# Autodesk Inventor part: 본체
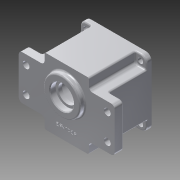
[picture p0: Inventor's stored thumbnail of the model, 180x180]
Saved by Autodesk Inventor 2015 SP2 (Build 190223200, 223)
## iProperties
Created: 2015-06
Part Number: 본체
Material: 알루미늄 6061
Document SubType Name: Modeling
Designer: AMC
Density: 2.7 g/cm^3
Appearance: 알루미늄 - 평지
Mass: 759.107 g
Surface Area: 671.501 cm^2
Volume: 281.151 cm^3
Author: AMC
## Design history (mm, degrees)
sketch "스케치1"
  geometry: L1 (65, 30)-(-65, 30); L2 (-65, 30)-(-65, -30); L3 (-65, -30)-(65, -30); L4 (65, -30)-(65, 30); 3 further points
  constraints: 8 end point, 2 midpoint, 2 parallel, 1 horizontal, 1 horizontal alignment, 1 perpendicular, 1 vertical alignment
  dimensions: "d0" = 130 distance of L1.start L1.end; "d1" = 60 distance of L1.end L2.end
extrude "돌출1" new body sketch "스케치1" distance "d2" = 12; taper "d3" = 0 deg
sketch "스케치2"
  geometry: L1 (-65, -30)-(-65, 30) reference; L2 (-65, 30)-(65, 30) reference; L3 (65, 30)-(65, -30) reference; L4 (65, -30)-(-65, -30) reference; L5 (-65, 30)-(65, 30) reference; L6 (-30, 45)-(30, 45); L7 (30, 45)-(30, 30); L8 (30, 30)-(-30, 30); L9 (-30, 30)-(-30, 45); 2 further points
  constraints: 8 end point, 2 parallel, 1 horizontal, 1 midpoint, 1 perpendicular, 1 point on line, 1 vertical alignment
  dimensions: "d4" = 60 distance of L6.start L6.end; "d5" = 45 distance from line of point (0, 0) L6
extrude "돌출2" join sketch "스케치2" distance "d6" = 70; taper "d7" = 0 deg
sketch "스케치3"
  geometry: L1 (-30, 45)-(30, 45) reference; L2 (30, 45)-(30, 30) reference; L3 (30, 30)-(65, 30) reference; L4 (65, 30)-(65, -30) reference; L5 (65, -30)-(-65, -30) reference; L6 (-65, -30)-(-65, 30) reference; L7 (-65, 30)-(-30, 30) reference; L8 (-30, 30)-(-30, 45) reference; L9 (-30, -30)-(30, -30); L10 (30, -30)-(30, -45); L11 (30, -45)-(-30, -45); L12 (-30, -45)-(-30, -30); 2 further points
  constraints: 8 end point, 2 parallel, 1 horizontal, 1 midpoint, 1 perpendicular, 1 point on line, 1 vertical alignment
  dimensions: "d8" = 45 distance from line of point (0, 0) L11; "d9" = 60 distance of L10.end L11.end
extrude "돌출3" join sketch "스케치3" distance "d10" = 70; taper "d11" = 0 deg
sketch "스케치4"
  geometry: L1 (-30, 45)-(30, 45) reference; L2 (30, 45)-(30, 30) reference; L3 (30, 30)-(-30, 30) reference; L4 (-30, 30)-(-30, 45) reference; L5 (30, -45)-(-30, -45) reference; L6 (-30, -45)-(-30, -30) reference; L7 (-30, -30)-(30, -30) reference; L8 (30, -30)-(30, -45) reference; L9 (45, -45)-(-45, -45); L10 (-45, -45)-(-45, 45); L11 (-45, 45)-(45, 45); L12 (45, 45)-(45, -45); 3 further points
  constraints: 8 end point, 2 collinear, 2 midpoint, 2 parallel, 1 horizontal, 1 horizontal alignment, 1 perpendicular, 1 vertical alignment
  dimensions: "d12" = 90 distance of L9.start L9.end; "d13" = 45 distance from line of point (0, 0) L10
extrude "돌출4" join sketch "스케치4" distance "d14" = 7; taper "d15" = 0 deg
sketch "스케치5"
  geometry: L1 (-30, 30)-(30, 30) reference; L2 (-30, 30)-(30, 30); L3 (30, 30)-(30, -30); L4 (30, -30)-(-30, -30); L5 (-30, -30)-(-30, 30); 1 further point
  constraints: 8 end point, 2 parallel, 1 horizontal, 1 perpendicular
  dimensions: "d17" = 60 distance of L2.end L3.end; "d18" = 30 distance from line of point (0, 0) L3
extrude "돌출5" join sketch "스케치5" stored distance "d19" = 7; taper "d20" = 0 deg
sketch "스케치6"
  geometry: L1 (45, -45)-(45, 45) reference; L2 (30, 30)-(30, -30); L3 (30, 30)-(45, 30); L4 (45, 30)-(45, -30); L5 (45, -30)-(30, -30); L6 (45, -45)-(45, 45) reference; 1 further point
  constraints: 8 end point, 2 point on line, 1 perpendicular, 1 vertical
extrude "돌출6" join sketch "스케치6" stored distance "d21" = 7; taper "d22" = 0 deg
sketch "스케치8"
  geometry: L1 (30, -30)-(30, -45) reference; L2 (30, -45)-(-30, -45) reference; L3 (-30, -45)-(-30, -30) reference; L4 (-30, -30)-(-65, -30) reference; L5 (-65, -30)-(-65, 30) reference; L6 (-65, 30)-(-30, 30) reference; L7 (-30, 30)-(-30, 45) reference; L8 (-30, 45)-(30, 45) reference; L9 (30, 45)-(30, 30) reference; L10 (30, 30)-(65, 30) reference; L11 (65, 30)-(65, -30) reference; L12 (65, -30)-(30, -30) reference; C1 r 4.5 at (-55, 17.5); 1 further point
  constraints: 1 centre point
  dimensions: "d23" = 9 diameter of C1; "d25" = 55 horizontal distance of C1.centre point (0, 0); "d26" = 17.5 vertical distance of point (0, 0) C1.centre
extrude "돌출7" cut sketch "스케치8" distance "d27" = 28; taper "d28" = 0 deg
sketch "스케치9"
  geometry: L1 (-45, -45)-(-45, -30) reference; L2 (-45, -30)-(-45, 30) reference; L3 (-45, 30)-(-45, 45) reference; L4 (-45, 45)-(-30, 45) reference; L5 (-30, 45)-(30, 45) reference; L6 (30, 45)-(45, 45) reference; L7 (45, 45)-(45, 30) reference; L8 (45, 30)-(45, -30) reference; L9 (45, -30)-(30, -30) reference; L10 (30, -30)-(30, -45) reference; L11 (45, -45)-(30, -45) reference; L12 (45, -30)-(45, -45) reference; L13 (-30, -45)-(-45, -45) reference; L14 (-30, -45)-(-30, -30) reference; L15 (-30, -30)-(-45, -30) reference; L16 (-45, 30)-(-30, 30) reference; L17 (-30, 30)-(-30, 45) reference; L18 (30, 45)-(30, 30) reference; L19 (30, 30)-(45, 30) reference; L20 (30, -45)-(-30, -45) reference; C1 r 3.5 at (37, -37); 1 further point
  constraints: 1 centre point
  dimensions: "d29" = 7 diameter of C1; "d30" = 37 horizontal distance of point (0, 0) C1.centre; "d31" = 37 horizontal distance of point (0, 0) C1.centre
extrude "돌출8" cut sketch "스케치9" distance "d32" = 28; taper "d33" = 0 deg
sketch "스케치10"
  geometry: L1 (30, -30)-(30, -45) reference; L2 (30, -45)-(-30, -45) reference; L3 (-30, -45)-(-30, -30) reference; L4 (-30, -30)-(-65, -30) reference; L5 (-65, -30)-(-65, 30) reference; L6 (-65, 30)-(-30, 30) reference; L7 (-30, 30)-(-30, 45) reference; L8 (-30, 45)-(30, 45) reference; L9 (30, 45)-(30, 30) reference; L10 (30, 30)-(65, 30) reference; L11 (65, 30)-(65, -30) reference; L12 (65, -30)-(30, -30) reference; C1 r 4.5 at (55, -17.5) reference; C2 r 4.5 at (-55, -17.5) reference; C3 r 4.5 at (55, 17.5) reference; C4 r 4.5 at (-55, 17.5) reference; C5 r 25 at (0, 11); 1 further point
  constraints: 1 centre point, 1 vertical alignment
  dimensions: "d34" = 50 diameter of C5; "d35" = 11 distance of point (0, 0) C5.centre
extrude "돌출9" join sketch "스케치10" distance "d36" = 7; taper "d37" = 0 deg
sketch "스케치11"
  geometry: C1 r 25 at (0, 0) reference; C2 r 16 at (0, 0); 1 further point
  constraints: 1 centre point, 1 coincident
  dimensions: "d38" = 32 diameter of C2
extrude "돌출10" cut sketch "스케치11" distance "d39" = 8; taper "d40" = 0 deg
sketch "스케치12"
  geometry: L1 (30, -41)-(30, -56) reference; L2 (30, -56)-(-30, -56) reference; L3 (-30, -56)-(-30, -41) reference; L4 (-30, -41)-(-65, -41) reference; L5 (-65, -41)-(-65, 19) reference; L6 (-65, 19)-(-30, 19) reference; L7 (-30, 19)-(-30, 34) reference; L8 (-30, 34)-(30, 34) reference; L9 (30, 34)-(30, 19) reference; L10 (30, 19)-(65, 19) reference; L11 (65, 19)-(65, -41) reference; L12 (65, -41)-(30, -41) reference; C1 r 16 at (0, 0) reference; C2 r 4.5 at (55, -28.5) reference; C3 r 4.5 at (-55, -28.5) reference; C4 r 4.5 at (55, 6.5) reference; C5 r 4.5 at (-55, 6.5) reference; C6 r 12.5 at (0, 0); 1 further point
  constraints: 1 centre point, 1 coincident
  dimensions: "d41" = 25 diameter of C6
extrude "돌출11" cut sketch "스케치12" distance "d42" = 5; taper "d43" = 0 deg
sketch "스케치13"
  geometry: L1 (30, -41)-(30, -56) reference; L2 (30, -56)-(-30, -56) reference; L3 (-30, -56)-(-30, -41) reference; L4 (-30, -41)-(-65, -41) reference; L5 (-65, -41)-(-65, 19) reference; L6 (-65, 19)-(-30, 19) reference; L7 (-30, 19)-(-30, 34) reference; L8 (-30, 34)-(30, 34) reference; L9 (30, 34)-(30, 19) reference; L10 (30, 19)-(65, 19) reference; L11 (65, 19)-(65, -41) reference; L12 (65, -41)-(30, -41) reference; C1 r 12.5 at (0, 0) reference; C2 r 4.5 at (55, -28.5) reference; C3 r 4.5 at (-55, -28.5) reference; C4 r 4.5 at (55, 6.5) reference; C5 r 4.5 at (-55, 6.5) reference; C6 r 17.5 at (0, 0); 1 further point
  constraints: 1 centre point, 1 coincident
  dimensions: "d44" = 35 diameter of C6
extrude "돌출12" cut sketch "스케치13" distance "d45" = 10; taper "d46" = 0 deg
sketch "스케치14"
  geometry: C1 r 40 at (0, 0); 1 further point
  constraints: 1 centre point, 1 coincident
  dimensions: "d47" = 80 diameter of C1
extrude "돌출13" cut sketch "스케치14" distance "d48" = 9; taper "d49" = 0 deg
sketch "스케치15"
  geometry: C1 r 39 at (0, 0); 1 further point
  constraints: 1 centre point, 1 coincident
  dimensions: "d50" = 78 diameter of C1
extrude "돌출14" cut sketch "스케치15" distance "d51" = 45; taper "d52" = 0 deg
sketch "스케치16"
  geometry: L1 (-45, -30)-(-45, 30) reference; L2 (-45, 30)-(-30, 30) reference; L3 (-30, 30)-(-30, 45) reference; L4 (-30, 45)-(30, 45) reference; L5 (30, 45)-(30, 30) reference; L6 (30, 30)-(45, 30) reference; L7 (45, 30)-(45, -30) reference; L8 (45, -30)-(30, -30) reference; L9 (30, -30)-(30, -45) reference; L10 (30, -45)-(-30, -45) reference; L11 (-30, -45)-(-30, -30) reference; L12 (-30, -30)-(-45, -30) reference; L13 (0, 0)-(24.749, 24.749); L14 (0, 0)-(35, 0); C1 r 40 at (0, 0) reference; A1 r 39 centre (0, 0) between (23.251, 31.312) and (31.312, 23.251) reference; A2 r 4 centre (24.749, 24.749) between (22.981, 28.337) and (28.337, 22.981); A3 r 1.75 centre (22.207, 29.907) between (22.981, 28.337) and (23.251, 31.312); A4 r 1.75 centre (29.907, 22.207) between (31.312, 23.251) and (28.337, 22.981); 2 further points
  constraints: 8 point on circle, 4 end point, 4 tangent, 3 centre point, 2 coincident, 1 equal length, 1 horizontal
  dimensions: "d53" = 35 distance of L13.start L13.end; "d54" = 45 deg angle of L14 L13; "d55" = 8 diameter of A2; "d56" = 3.5 diameter of A3; "d57" = 3.5 diameter of A4
extrude "돌출15" join sketch "스케치16" distance "d58" = 45; taper "d59" = 0 deg
hole "구멍1" diameter "d62" = 3.459; stored, may be unused: countersink angle "d66" = 90 deg, drill point angle "d68" = 118 deg; dims "d60" = 10, "d61" = 10, "d63" = 12, "d64" = 4, "d65" = 2, "d67" = 15
sketch "스케치17"
  geometry: L1 (30, -30)-(30, -45) reference; L2 (30, -45)-(-30, -45) reference; L3 (-30, -45)-(-30, -30) reference; L4 (-30, -30)-(-65, -30) reference; L5 (-65, -30)-(-65, 30) reference; L6 (-65, 30)-(-30, 30) reference; L7 (-30, 30)-(-30, 45) reference; L8 (-30, 45)-(30, 45) reference; L9 (30, 45)-(30, 30) reference; L10 (30, 30)-(65, 30) reference; L11 (65, 30)-(65, -30) reference; L12 (65, -30)-(30, -30) reference; C1 r 16 at (0, 11) reference; C2 r 25 at (0, 11) reference; C3 r 4.5 at (55, -17.5) reference; C4 r 4.5 at (-55, -17.5) reference; C5 r 4.5 at (55, 17.5) reference; C6 r 4.5 at (-55, 17.5) reference; 2 further points
  constraints: 1 vertical alignment, 1 other
  dimensions: "d72" = 15 distance from line of point (0, -30) L2
feature "엠보싱1" sketch "스케치17" dims "d73" = 0.5, "d74" = 0
fillet "모깎기1" dims "d75" = 5
fillet "모깎기2" dims "d76" = 0.3
sketch "스케치18"
  geometry: L1 (-45, -30)-(-45, 30) reference; L2 (-45, 30)-(-30, 30) reference; L3 (-30, 30)-(-30, 45) reference; L4 (-30, 45)-(30, 45) reference; L5 (30, 45)-(30, 30) reference; L6 (30, 30)-(45, 30) reference; L7 (45, 30)-(45, -30) reference; L8 (45, -30)-(30, -30) reference; L9 (30, -30)-(30, -45) reference; L10 (30, -45)-(-30, -45) reference; L11 (-30, -45)-(-30, -30) reference; L12 (-30, -30)-(-45, -30) reference; C1 r 17.5 at (0, -11) reference; C2 r 11 at (0, 20); A1 r 1.75 centre (29.907, -22.207) between (28.337, -22.981) and (31.312, -23.251) reference; A2 r 39 centre (0, 0) between (31.312, -23.251) and (31.312, 23.251) reference; A3 r 1.75 centre (29.907, 22.207) between (31.312, 23.251) and (28.337, 22.981) reference; A4 r 4 centre (24.749, 24.749) between (22.981, 28.337) and (28.337, 22.981) reference; A5 r 1.75 centre (22.207, 29.907) between (22.981, 28.337) and (23.251, 31.312) reference; A6 r 39 centre (0, 0) between (23.251, 31.312) and (-23.251, 31.312) reference; A7 r 1.75 centre (-22.207, 29.907) between (-23.251, 31.312) and (-22.981, 28.337) reference; A8 r 4 centre (-24.749, 24.749) between (-28.337, 22.981) and (-22.981, 28.337) reference; A9 r 1.75 centre (-29.907, 22.207) between (-28.337, 22.981) and (-31.312, 23.251) reference; A10 r 39 centre (0, 0) between (-31.312, 23.251) and (-31.312, -23.251) reference; A11 r 1.75 centre (-29.907, -22.207) between (-31.312, -23.251) and (-28.337, -22.981) reference; A12 r 4 centre (-24.749, -24.749) between (-22.981, -28.337) and (-28.337, -22.981) reference; A13 r 1.75 centre (-22.207, -29.907) between (-22.981, -28.337) and (-23.251, -31.312) reference; A14 r 39 centre (0, 0) between (-23.251, -31.312) and (23.251, -31.312) reference; A15 r 1.75 centre (22.207, -29.907) between (23.251, -31.312) and (22.981, -28.337) reference; A16 r 4 centre (24.749, -24.749) between (28.337, -22.981) and (22.981, -28.337) reference; 1 further point
  constraints: 1 centre point, 1 vertical alignment
  dimensions: "d77" = 22 diameter of C2; "d78" = 20 distance of point (0, 0) C2.centre
extrude "돌출16" cut sketch "스케치18" distance "d79" = 7; taper "d80" = 0 deg
sketch "스케치19"
  geometry: L1 (30, 25)-(30, 10) reference; L2 (30, 10)-(60, 10) reference; L3 (65, 5)-(65, -45) reference; L4 (60, -50)-(30, -50) reference; L5 (30, -50)-(30, -65) reference; L6 (30, -65)-(-30, -65) reference; L7 (-30, -65)-(-30, -50) reference; L8 (-30, -50)-(-60, -50) reference; L9 (-65, -45)-(-65, 5) reference; L10 (-60, 10)-(-30, 10) reference; L11 (-30, 10)-(-30, 25) reference; L12 (-30, 25)-(30, 25) reference; C1 r 11 at (0, 0) reference; C2 r 17.5 at (0, -31) reference; C3 r 4.5 at (55, -2.5) reference; C4 r 4.5 at (-55, -2.5) reference; C5 r 4.5 at (55, -37.5) reference; C6 r 4.5 at (-55, -37.5) reference; C7 r 9.5 at (0, 0); A1 r 5 centre (60, 5) between (65, 5) and (60, 10) reference; A2 r 5 centre (60, -45) between (60, -50) and (65, -45) reference; A3 r 5 centre (-60, -45) between (-65, -45) and (-60, -50) reference; A4 r 5 centre (-60, 5) between (-60, 10) and (-65, 5) reference; 1 further point
  constraints: 1 centre point, 1 coincident
  dimensions: "d81" = 19 diameter of C7
extrude "돌출17" cut sketch "스케치19" distance "d82" = 1; taper "d83" = 0 deg
fillet "모깎기3" dims "d84" = 0.3
fillet "모깎기4" dims "d89" = 2
sketch "스케치22"
  geometry: L1 (-45, -30)-(-45, 30) reference; L2 (-45, 30)-(-30, 30) reference; L3 (-30, 30)-(-30, 45) reference; L4 (-30, 45)-(30, 45) reference; L5 (30, 45)-(30, 30) reference; L6 (30, 30)-(45, 30) reference; L7 (45, 30)-(45, -30) reference; L8 (45, -30)-(30, -30) reference; L9 (30, -30)-(30, -45) reference; L10 (30, -45)-(-30, -45) reference; L11 (-30, -45)-(-30, -30) reference; L12 (-30, -30)-(-45, -30) reference; C1 r 11 at (0, 20) reference; C2 r 17.5 at (0, -11) reference; C3 r 7.768 at (0, 20) reference; A1 r 1.75 centre (29.907, -22.207) between (28.337, -22.981) and (31.312, -23.251) reference; A2 r 39 centre (0, 0) between (31.312, -23.251) and (31.312, 23.251) reference; A3 r 1.75 centre (29.907, 22.207) between (31.312, 23.251) and (28.337, 22.981) reference; A4 r 4 centre (24.749, 24.749) between (22.981, 28.337) and (28.337, 22.981) reference; A5 r 1.75 centre (22.207, 29.907) between (22.981, 28.337) and (23.251, 31.312) reference; A6 r 39 centre (0, 0) between (23.251, 31.312) and (-23.251, 31.312) reference; A7 r 1.75 centre (-22.207, 29.907) between (-23.251, 31.312) and (-22.981, 28.337) reference; A8 r 4 centre (-24.749, 24.749) between (-28.337, 22.981) and (-22.981, 28.337) reference; A9 r 1.75 centre (-29.907, 22.207) between (-28.337, 22.981) and (-31.312, 23.251) reference; A10 r 39 centre (0, 0) between (-31.312, 23.251) and (-31.312, -23.251) reference; A11 r 1.75 centre (-29.907, -22.207) between (-31.312, -23.251) and (-28.337, -22.981) reference; A12 r 4 centre (-24.749, -24.749) between (-22.981, -28.337) and (-28.337, -22.981) reference; A13 r 1.75 centre (-22.207, -29.907) between (-22.981, -28.337) and (-23.251, -31.312) reference; A14 r 39 centre (0, 0) between (-23.251, -31.312) and (23.251, -31.312) reference; A15 r 1.75 centre (22.207, -29.907) between (23.251, -31.312) and (22.981, -28.337) reference; A16 r 4 centre (24.749, -24.749) between (28.337, -22.981) and (22.981, -28.337) reference; A17 r 20.5 centre (0, -11) between (-7.402, 8.117) and (7.402, 8.117); A18 r 14 centre (0, 20) between (7.402, 8.117) and (-7.402, 8.117); 1 further point
  constraints: 4 point on circle, 2 centre point, 2 coincident
  dimensions: "d96" = 41 diameter of A17; "d97" = 28 diameter of A18
extrude "돌출19" join sketch "스케치22" distance "d98" = 7; taper "d99" = 0 deg
fillet "모깎기5" dims "d100" = 8
fillet "모깎기6" dims "d101" = 2
fillet "모깎기7" dims "d102" = 3
chamfer "모따기3" distance "d103" = 1; stored, may be unused: second distance "d104" = 2, angle "d105" = 45 deg
fillet "모깎기8" dims "d106" = 2
fillet "모깎기9" dims "d107" = 2
fillet "모깎기10" dims "d108" = 2
chamfer "모따기4" distance "d109" = 1; stored, may be unused: second distance "d110" = 2, angle "d111" = 45 deg
fillet "모깎기11" dims "d112" = 2
fillet "모깎기12" dims "d113" = 2
fillet "모깎기13" dims "d114" = 2
fillet "모깎기14" dims "d115" = 2
fillet "모깎기15" dims "d116" = 2
fillet "모깎기18" dims "d119" = 2
fillet "모깎기19" dims "d120" = 5
fillet "모깎기20" dims "d121" = 2
node "솔리드1"
mirror "대칭1"
mirror "대칭2"
mirror "대칭3"
mirror "대칭4"
mirror "대칭5"
pattern_circular "원형 패턴1" dims angle "d70" = 360 deg
node "절단 모서리 투영1"
node "절단 모서리 투영2"
node "절단 모서리 투영3"
node "절단 모서리 투영4"
node "절단 모서리 투영5"
node "절단 모서리 투영6"
node "절단 모서리 투영7"
node "절단 모서리 투영8"
node "절단 모서리 투영9"
node "절단 모서리 투영10"
node "절단 모서리 투영11"
node "절단 모서리 투영12"
node "절단 모서리 투영13"
node "절단 모서리 투영16"
